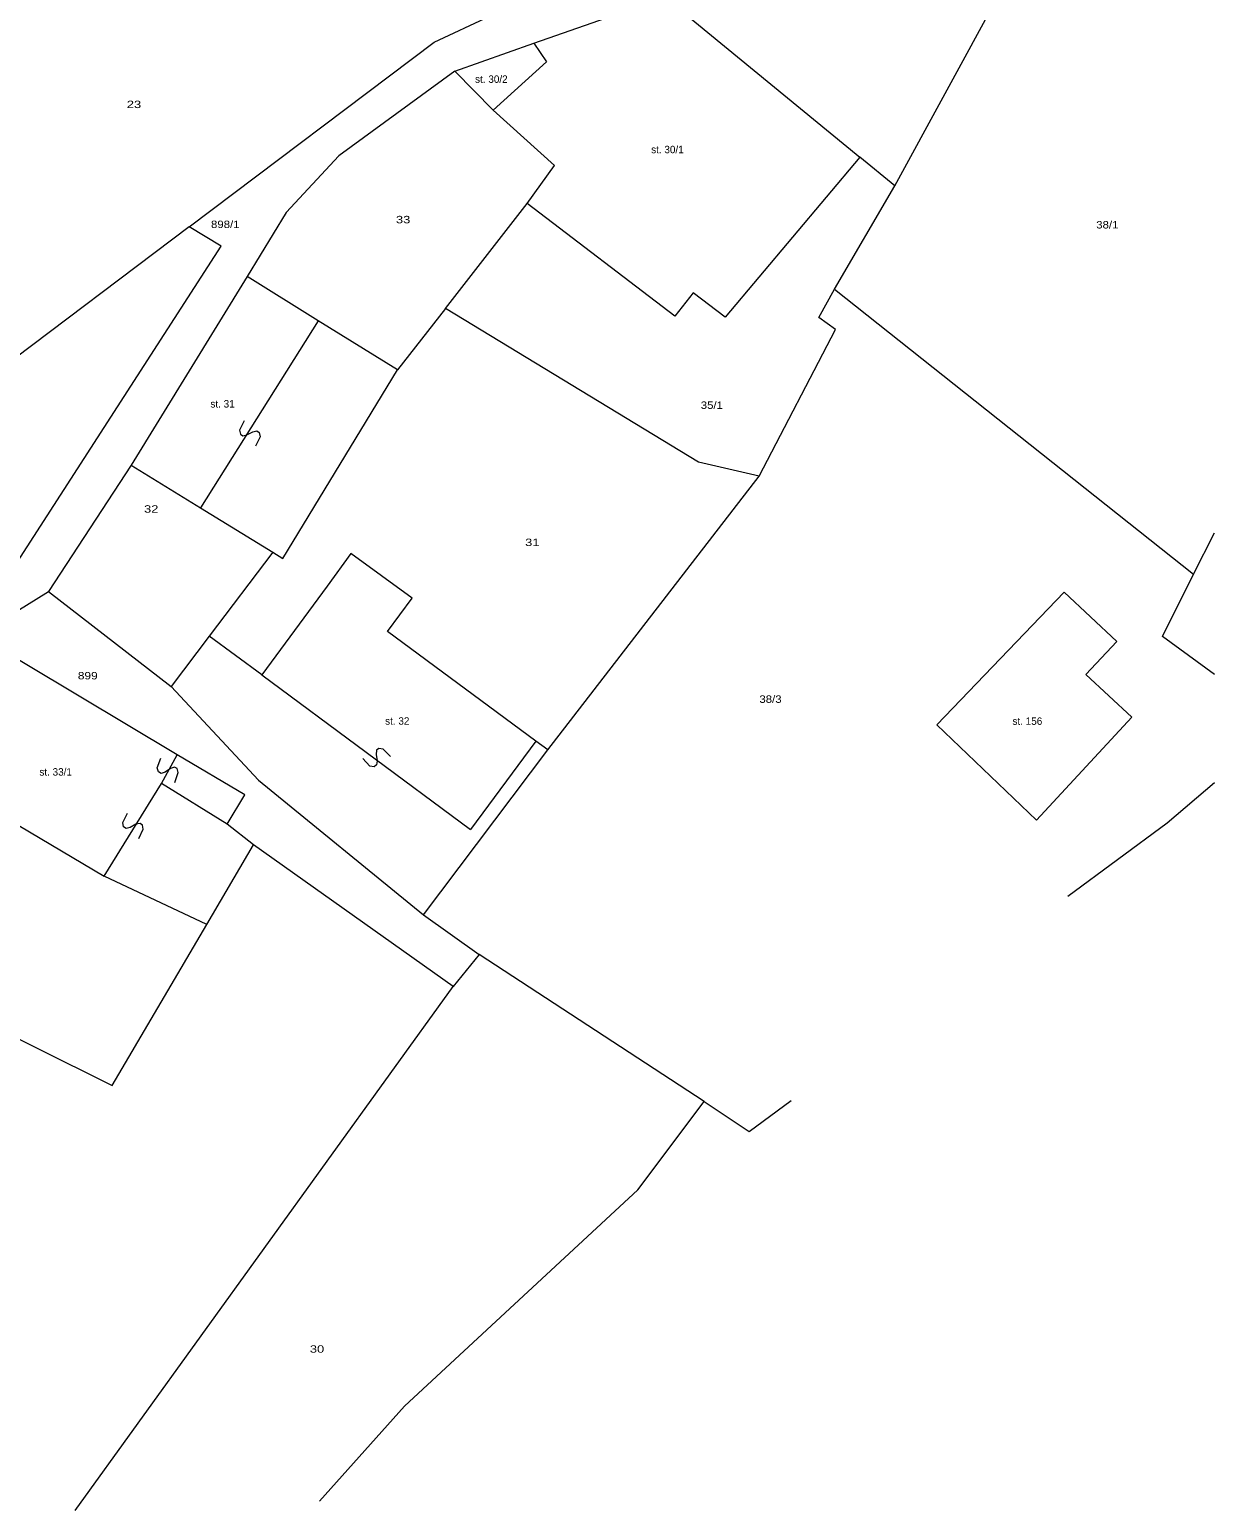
# Model space of a CAD drawing. Extents: x -694702 to -694000, y -1089746 to -1089192.
# Drawn here: x -694570.7 to -694490.9, y -1089367.9 to -1089268.2 of the extents above; entities that cross this region are included whole.
import ezdxf

# ---------------------------------------------------------------- set-up
doc = ezdxf.new("R2010")
doc.units = 0
doc.header["$LTSCALE"] = 0.2
doc.layers.add('50', color=7, linetype='Continuous', lineweight=13)
doc.layers.add('52', color=7, linetype='Continuous', lineweight=13)

msp = doc.modelspace()

# ---------------------------------------------------------------- linework, layer by layer
at = {"layer": '50'}
for p, q in [((-694512.47, -1089278.7), (-694501.32, -1089258.23)), ((-694527.95, -1089266), (-694514.82, -1089276.77)), ((-694539.53, -1089273.61), (-694542.11, -1089270.98)), ((-694512.47, -1089278.7), (-694514.82, -1089276.77)), ((-694516.54, -1089285.67), (-694512.47, -1089278.7)), ((-694542.74, -1089286.97), (-694537.23, -1089279.9)), ((-694560.01, -1089281.46), (-694572.97, -1089291.24)), ((-694556.09, -1089284.81), (-694563.91, -1089297.52)), ((-694542.74, -1089286.97), (-694545.97, -1089291.11)), ((-694551.31, -1089287.8), (-694559.23, -1089300.4)), ((-694563.91, -1089297.52), (-694569.47, -1089306.02)), ((-694535.84, -1089316.7), (-694521.61, -1089298.26)), ((-694554.37, -1089303.39), (-694558.65, -1089309.04)), ((-694574.26, -1089308.99), (-694569.47, -1089306.02)), ((-694569.47, -1089306.02), (-694561.22, -1089312.43)), ((-694558.65, -1089309.04), (-694561.22, -1089312.43)), ((-694555.1, -1089311.65), (-694541.05, -1089322.05)), ((-694536.65, -1089316.1), (-694541.05, -1089322.05)), ((-694579.11, -1089317.28), (-694565.73, -1089325.21)), ((-694561.86, -1089318.97), (-694560.8, -1089317.02)), ((-694544.21, -1089327.81), (-694535.84, -1089316.7)), ((-694565.73, -1089325.21), (-694561.86, -1089318.97)), ((-694557.44, -1089321.7), (-694561.86, -1089318.97)), ((-694542.21, -1089332.63), (-694555.66, -1089323.1)), ((-694558.81, -1089328.46), (-694565.73, -1089325.21)), ((-694525.32, -1089340.38), (-694540.47, -1089330.48)), ((-694567.67, -1089367.92), (-694542.21, -1089332.63))]:
    msp.add_line(p, q, dxfattribs=at)
for points in [[(-694542.11, -1089270.98), (-694536.78, -1089269.1), (-694527.95, -1089266)], [(-694560.01, -1089281.46), (-694543.5, -1089269.02), (-694539.75, -1089267.27)], [(-694536.78, -1089269.1), (-694535.93, -1089270.36), (-694539.53, -1089273.61)], [(-694542.11, -1089270.98), (-694549.92, -1089276.69), (-694553.46, -1089280.51), (-694556.09, -1089284.81)], [(-694537.23, -1089279.9), (-694535.39, -1089277.34), (-694539.53, -1089273.61)], [(-694514.82, -1089276.77), (-694523.9, -1089287.55), (-694526.05, -1089285.91), (-694527.28, -1089287.48), (-694537.23, -1089279.9)], [(-694580.26, -1089310.11), (-694579.15, -1089309.98), (-694576.37, -1089304.83), (-694572.27, -1089305.11), (-694557.85, -1089282.77), (-694560.01, -1089281.46)], [(-694545.97, -1089291.11), (-694551.31, -1089287.8), (-694556.09, -1089284.81)], [(-694521.61, -1089298.26), (-694516.46, -1089288.39), (-694517.58, -1089287.58), (-694516.54, -1089285.67), (-694492.35, -1089304.86)], [(-694521.61, -1089298.26), (-694525.69, -1089297.32), (-694542.74, -1089286.97)], [(-694554.37, -1089303.39), (-694553.68, -1089303.8), (-694545.97, -1089291.11)], [(-694563.91, -1089297.52), (-694559.23, -1089300.4), (-694554.37, -1089303.39)], [(-694490.94, -1089311.61), (-694494.44, -1089309.06), (-694492.35, -1089304.86), (-694490.94, -1089302.07)], [(-694535.84, -1089316.7), (-694536.65, -1089316.1), (-694546.63, -1089308.73), (-694544.98, -1089306.47), (-694549.11, -1089303.47), (-694550.7, -1089305.66), (-694555.1, -1089311.65), (-694558.65, -1089309.04)], [(-694555.66, -1089323.1), (-694557.44, -1089321.7), (-694556.26, -1089319.73), (-694560.8, -1089317.02), (-694574.26, -1089308.99)], [(-694561.22, -1089312.43), (-694555.33, -1089318.73), (-694544.21, -1089327.81)], [(-694500.81, -1089326.56), (-694494.12, -1089321.62), (-694490.94, -1089318.89)], [(-694585.96, -1089328.98), (-694565.18, -1089339.31), (-694558.81, -1089328.46), (-694555.66, -1089323.1)], [(-694544.21, -1089327.81), (-694540.47, -1089330.48), (-694542.21, -1089332.63)], [(-694551.23, -1089367.3), (-694545.5, -1089360.91), (-694529.77, -1089346.33), (-694525.32, -1089340.38)], [(-694525.32, -1089340.38), (-694522.27, -1089342.4), (-694519.45, -1089340.32)]]:
    msp.add_lwpolyline(points, dxfattribs=at)
msp.add_lwpolyline([(-694496.49, -1089314.49), (-694499.6, -1089311.61), (-694497.52, -1089309.4), (-694501.05, -1089306.07), (-694509.63, -1089315.02), (-694502.93, -1089321.44)], close=True, dxfattribs=at)
at = {"layer": '52'}
for points in [[(-694556.305, -1089294.525), (-694556.604, -1089295.158), (-694556.552, -1089295.439), (-694556.386, -1089295.554), (-694556.109, -1089295.489), (-694555.722, -1089295.267), (-694555.449, -1089295.211), (-694555.278, -1089295.317), (-694555.218, -1089295.603), (-694555.526, -1089296.232)], [(-694546.443, -1089317.151), (-694546.933, -1089316.651), (-694547.214, -1089316.602), (-694547.38, -1089316.718), (-694547.415, -1089317), (-694547.341, -1089317.44), (-694547.383, -1089317.715), (-694547.541, -1089317.839), (-694547.83, -1089317.796), (-694548.313, -1089317.289)], [(-694560.976, -1089318.886), (-694560.734, -1089318.229), (-694560.81, -1089317.954), (-694560.986, -1089317.854), (-694561.256, -1089317.943), (-694561.622, -1089318.198), (-694561.889, -1089318.278), (-694562.068, -1089318.187), (-694562.153, -1089317.908), (-694561.902, -1089317.255)], [(-694563.401, -1089322.675), (-694563.096, -1089322.045), (-694563.145, -1089321.763), (-694563.311, -1089321.647), (-694563.588, -1089321.709), (-694563.977, -1089321.928), (-694564.25, -1089321.982), (-694564.42, -1089321.874), (-694564.478, -1089321.588), (-694564.165, -1089320.962)]]:
    msp.add_lwpolyline(points, dxfattribs=at)

# ---------------------------------------------------------------- texts
for s, p in [('st. 30/2', (-694540.74, -1089271.77)), ('st. 30/1', (-694528.88, -1089276.51)), ('st. 31', (-694558.57, -1089293.64)), ('st. 32', (-694546.8, -1089315)), ('st. 156', (-694504.54, -1089315.01)), ('st. 33/1', (-694570.09, -1089318.43))]:
    msp.add_text(s, height=0.5, dxfattribs=at).set_placement(p)
for s, width, p in [('23', 1.3, (-694564.2, -1089273.47)), ('33', 1.3, (-694546.07, -1089281.23)), ('898/1', 1.15, (-694558.53, -1089281.55)), ('38/1', 1.15, (-694498.9, -1089281.58)), ('35/1', 1.15, (-694525.54, -1089293.73)), ('32', 1.3, (-694563.04, -1089300.72)), ('31', 1.3, (-694537.37, -1089302.97)), ('899', 1.2, (-694567.5, -1089311.95)), ('38/3', 1.15, (-694521.59, -1089313.53)), ('30', 1.3, (-694551.87, -1089357.3))]:
    msp.add_text(s, height=0.5, dxfattribs=dict(at, width=width)).set_placement(p)

doc.saveas('drawing.dxf')
